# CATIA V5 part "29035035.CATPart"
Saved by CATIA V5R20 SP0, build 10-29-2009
Part number: 29035035
Definition: NONE
Nomenclature: 29035035
Source: Unknown
Description: 29035035
Bounding box of the stored display mesh (mm): x -17.5 to 44.548, y -31.5 to 66.048, z -21.5 to 21.5
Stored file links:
  C:\Users\Utente\Desktop\IO LAVORO\3D X SITO CF\X SITO\PLASTICA\RF1\29035035.CATPart
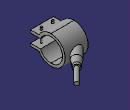
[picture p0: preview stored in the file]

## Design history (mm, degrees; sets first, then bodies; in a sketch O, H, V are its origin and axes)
Body1 "29035035" (main body)
  Solid1: solid without history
